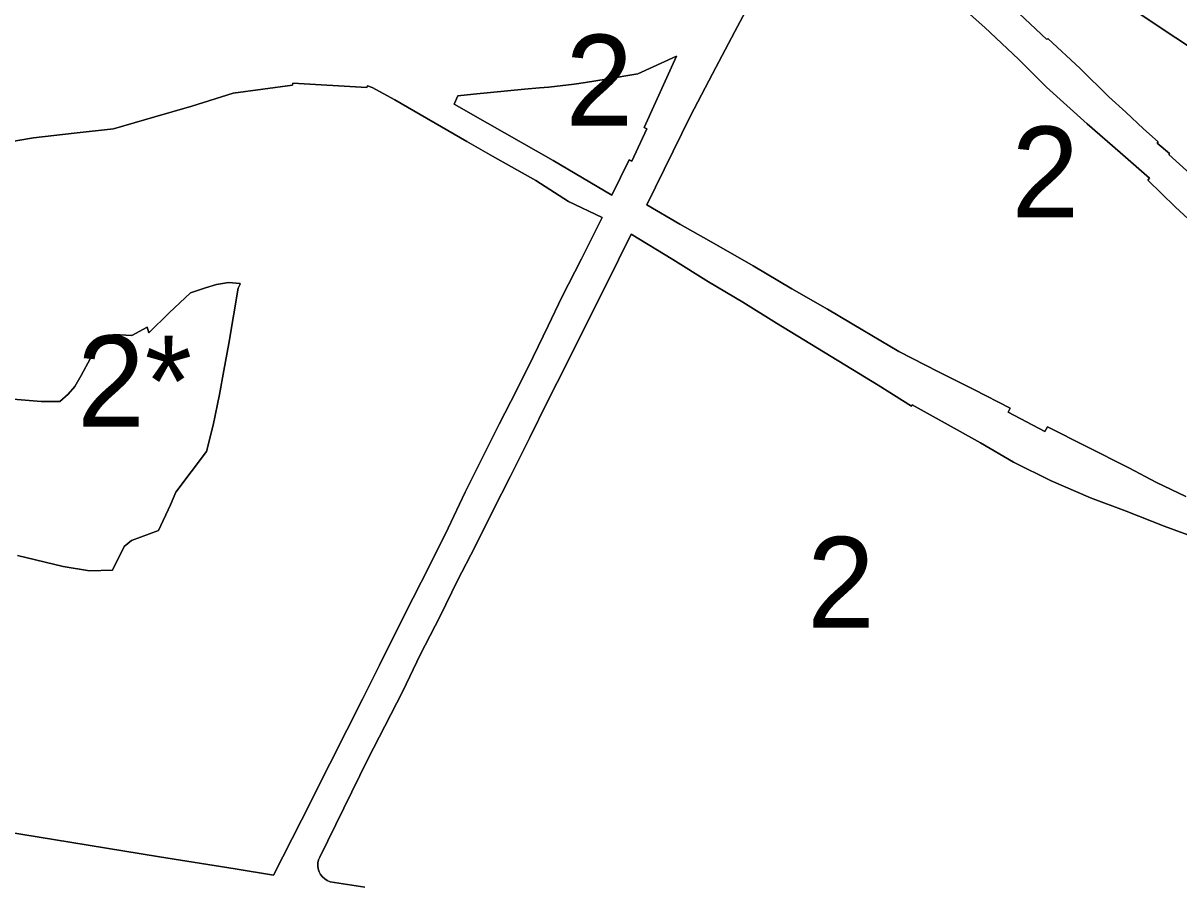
# Model space of a CAD drawing. Extents: x 598968 to 613553, y 4409678 to 4430833.
# Drawn here: x 607715.2 to 607867.8, y 4416289 to 4416402.7 of the extents above; entities that cross this region are included whole.
import ezdxf

# ---------------------------------------------------------------- set-up
doc = ezdxf.new("R2010")
doc.units = 0
for name, color, linetype in [('1', 7, 'Continuous'), ('ZONA 2. CARRERS DE CASES. Cases de trast', 7, 'Continuous'), ("ZONA 2_. CARRERS DE CASES. Afectades a ús d'aparcament", 7, 'Continuous')]:
    doc.layers.add(name, color=color, linetype=linetype)

msp = doc.modelspace()

# ---------------------------------------------------------------- linework, layer by layer
at = {"layer": '1'}
for points in [[(607833.2751, 4416410.0535), (607842.1551, 4416402.1438), (607846.625, 4416397.9639), (607850.315, 4416394.264), (607855.6849, 4416389.4042), (607860.0249, 4416385.6143), (607863.9149, 4416382.2344), (607863.6749, 4416381.9644), (607867.3149, 4416378.4645), (607877.7248, 4416368.8498)], [(607868.715, 4416340.245), (607864.8212, 4416342.0745), (607861.175, 4416344.0349), (607855.6051, 4416346.8447), (607850.4351, 4416349.4546), (607850.0951, 4416348.8246), (607845.2338, 4416351.3794), (607845.5063, 4416351.9116), (607840.7152, 4416354.3643), (607836.0753, 4416356.7042), (607830.8053, 4416359.3541), (607826.0654, 4416362.204), (607821.3954, 4416364.9639), (607816.6755, 4416367.6537), (607811.5655, 4416370.6636), (607806.7556, 4416373.4435), (607801.8956, 4416376.1734), (607797.5557, 4416378.7133), (607803.3055, 4416390.4532), (607806.2155, 4416396.0332), (607809.162, 4416401.5938), (607811.6354, 4416406.2732)], [(607869.2898, 4416382.8195), (607866.4748, 4416385.3744), (607866.5548, 4416385.4844), (607864.9326, 4416386.8721), (607865.0703, 4416387.033), (607863.1349, 4416388.7443), (607860.7749, 4416390.9542), (607858.5349, 4416392.9642), (607854.7549, 4416396.7141), (607850.5011, 4416400.6895), (607850.365, 4416400.5439), (607845.9477, 4416404.682)], [(607860.5903, 4416405.2824), (607864.9348, 4416402.4042), (607869.8548, 4416399.1343)], [(607711.1266, 4416386.6417), (607716.5566, 4416387.5518), (607721.9565, 4416388.1918), (607727.1364, 4416388.7419), (607732.5864, 4416390.332), (607737.4724, 4416391.7408), (607742.9162, 4416393.4522), (607750.7861, 4416394.5123), (607750.8161, 4416394.7623), (607760.596, 4416394.2225), (607760.686, 4416394.4225), (607761.276, 4416394.2325), (607764.256, 4416392.5825), (607773.7959, 4416387.0828), (607777.1559, 4416385.1629), (607782.8958, 4416381.953), (607787.2058, 4416379.1831), (607791.6657, 4416377.0432), (607788.9358, 4416371.6132), (607786.3458, 4416366.5432), (607784.5159, 4416362.7432), (607782.5459, 4416358.6633), (607780.3259, 4416354.2333), (607778.0464, 4416349.7726), (607773.5661, 4416340.8134), (607771.3161, 4416336.0834), (607768.8661, 4416331.0734), (607766.7162, 4416326.8834), (607764.6262, 4416322.7634), (607762.2563, 4416318.0034), (607759.9963, 4416313.4834), (607757.9263, 4416309.4035), (607755.7164, 4416304.9835), (607754.4414, 4416302.4735), (607753.1664, 4416299.9635), (607748.2765, 4416290.2935), (607743.1766, 4416291.1034), (607733.2267, 4416292.6732), (607723.7818, 4416294.238), (607708.397, 4416296.7227)], [(607760.3364, 4416288.6937), (607755.7264, 4416289.3937), (607755.3576, 4416289.5517), (607755.0211, 4416289.77), (607754.7266, 4416290.0425), (607754.4828, 4416290.3611), (607754.2968, 4416290.7166), (607754.1739, 4416291.0985), (607754.1177, 4416291.4958), (607754.13, 4416291.8968), (607754.2104, 4416292.2899), (607754.3564, 4416292.6636), (607760.7263, 4416305.5836), (607762.9663, 4416309.9535), (607765.3362, 4416314.5635), (607767.6362, 4416319.3435), (607770.2462, 4416324.4435), (607772.5561, 4416329.1635), (607774.8761, 4416333.6635), (607777.226, 4416338.3435), (607779.536, 4416342.9334), (607782.0859, 4416348.0334), (607784.4459, 4416352.7734), (607786.9758, 4416357.7733), (607789.0058, 4416361.9033), (607791.2858, 4416366.4133), (607793.7857, 4416371.4833), (607795.4957, 4416374.8433), (607800.9678, 4416371.5254), (607805.6956, 4416368.5835), (607810.2056, 4416365.8637), (607814.6755, 4416363.1238), (607823.6954, 4416357.614), (607828.1054, 4416354.9241), (607832.4715, 4416352.1603), (607832.5753, 4416352.3242), (607836.9353, 4416349.9243), (607841.6053, 4416347.3144), (607845.9552, 4416344.7745), (607850.9152, 4416342.3247), (607856.1051, 4416340.0548), (607860.8251, 4416338.2849), (607865.845, 4416336.345), (607870.285, 4416334.7051)]]:
    msp.add_lwpolyline(points, dxfattribs=at)
msp.add_lwpolyline([(607787.9657, 4416394.6429), (607789.4597, 4416394.8879), (607792.1757, 4416395.333), (607796.3511, 4416396.0226), (607801.4755, 4416398.3431), (607797.1756, 4416388.9532), (607797.5556, 4416388.7632), (607795.5457, 4416384.4732), (607795.2157, 4416384.6532), (607792.9057, 4416380.0032), (607785.1758, 4416384.573), (607776.4959, 4416389.4928), (607772.1245, 4416392.023), (607772.6059, 4416393.1027), (607774.6459, 4416393.3527), (607781.4058, 4416394.0028), (607783.3729, 4416394.1571), (607784.5957, 4416394.2529)], close=True, dxfattribs=at)
at = {"layer": 'ZONA 2. CARRERS DE CASES. Cases de trast'}
for points in [[(607877.7248, 4416368.8498), (607867.3149, 4416378.4645), (607863.6749, 4416381.9644), (607863.9149, 4416382.2344), (607860.0249, 4416385.6143), (607855.6849, 4416389.4042), (607850.315, 4416394.264), (607846.625, 4416397.9639), (607842.1551, 4416402.1438), (607833.2751, 4416410.0535)], [(607811.6354, 4416406.2732), (607809.162, 4416401.5938), (607806.2155, 4416396.0332), (607803.3055, 4416390.4532), (607797.5557, 4416378.7133), (607801.8956, 4416376.1734), (607806.7556, 4416373.4435), (607811.5655, 4416370.6636), (607816.6755, 4416367.6537), (607821.3954, 4416364.9639), (607826.0654, 4416362.204), (607830.8053, 4416359.3541), (607836.0753, 4416356.7042), (607840.7152, 4416354.3643), (607845.5063, 4416351.9116), (607845.2338, 4416351.3794), (607850.0951, 4416348.8246), (607850.4351, 4416349.4546), (607855.6051, 4416346.8447), (607861.175, 4416344.0349), (607864.8212, 4416342.0745), (607868.715, 4416340.245)], [(607845.9477, 4416404.682), (607850.365, 4416400.5439), (607850.5011, 4416400.6895), (607854.7549, 4416396.7141), (607858.5349, 4416392.9642), (607860.7749, 4416390.9542), (607863.1349, 4416388.7443), (607865.0703, 4416387.033), (607864.9326, 4416386.8721), (607866.5548, 4416385.4844), (607866.4748, 4416385.3744), (607869.2898, 4416382.8195)], [(607869.8548, 4416399.1343), (607864.9348, 4416402.4042), (607860.5903, 4416405.2824)], [(607708.397, 4416296.7227), (607723.7818, 4416294.238), (607733.2267, 4416292.6732), (607743.1766, 4416291.1034), (607748.2765, 4416290.2935), (607753.1664, 4416299.9635), (607754.4414, 4416302.4735), (607755.7164, 4416304.9835), (607757.9263, 4416309.4035), (607759.9963, 4416313.4834), (607762.2563, 4416318.0034), (607764.6262, 4416322.7634), (607766.7162, 4416326.8834), (607768.8661, 4416331.0734), (607771.3161, 4416336.0834), (607773.5661, 4416340.8134), (607778.0464, 4416349.7726), (607780.3259, 4416354.2333), (607782.5459, 4416358.6633), (607784.5159, 4416362.7432), (607786.3458, 4416366.5432), (607788.9358, 4416371.6132), (607791.6657, 4416377.0432), (607787.2058, 4416379.1831), (607782.8958, 4416381.953), (607777.1559, 4416385.1629), (607773.7959, 4416387.0828), (607764.256, 4416392.5825), (607761.276, 4416394.2325), (607760.686, 4416394.4225), (607760.596, 4416394.2225), (607750.8161, 4416394.7623), (607750.7861, 4416394.5123), (607742.9162, 4416393.4522), (607737.4724, 4416391.7408), (607732.5864, 4416390.332), (607727.1364, 4416388.7419), (607721.9565, 4416388.1918), (607716.5566, 4416387.5518), (607711.1266, 4416386.6417)], [(607870.285, 4416334.7051), (607865.845, 4416336.345), (607860.8251, 4416338.2849), (607856.1051, 4416340.0548), (607850.9152, 4416342.3247), (607845.9552, 4416344.7745), (607841.6053, 4416347.3144), (607836.9353, 4416349.9243), (607832.5753, 4416352.3242), (607832.4715, 4416352.1603), (607828.1054, 4416354.9241), (607823.6954, 4416357.614), (607814.6755, 4416363.1238), (607810.2056, 4416365.8637), (607805.6956, 4416368.5835), (607800.9678, 4416371.5254), (607795.4957, 4416374.8433), (607793.7857, 4416371.4833), (607791.2858, 4416366.4133), (607789.0058, 4416361.9033), (607786.9758, 4416357.7733), (607784.4459, 4416352.7734), (607782.0859, 4416348.0334), (607779.536, 4416342.9334), (607777.226, 4416338.3435), (607774.8761, 4416333.6635), (607772.5561, 4416329.1635), (607770.2462, 4416324.4435), (607767.6362, 4416319.3435), (607765.3362, 4416314.5635), (607762.9663, 4416309.9535), (607760.7263, 4416305.5836), (607754.3564, 4416292.6636), (607754.2104, 4416292.2899), (607754.13, 4416291.8968), (607754.1177, 4416291.4958), (607754.1739, 4416291.0985), (607754.2968, 4416290.7166), (607754.4828, 4416290.3611), (607754.7266, 4416290.0425), (607755.0211, 4416289.77), (607755.3576, 4416289.5517), (607755.7264, 4416289.3937), (607760.3364, 4416288.6937)], [(607713.8967, 4416353.0876), (607717.5988, 4416352.7577), (607720.0666, 4416352.7877), (607721.1336, 4416353.7251), (607722.0117, 4416354.773), (607722.8666, 4416356.1877), (607724.0666, 4416358.3977), (607724.9781, 4416359.718), (607726.4965, 4416361.4277), (607727.2151, 4416361.6344), (607729.5365, 4416361.5028), (607731.5665, 4416362.5978), (607731.8009, 4416361.8498), (607734.4864, 4416364.4778), (607737.309, 4416367.1211), (607739.2796, 4416367.7718), (607740.7463, 4416368.2079), (607742.3363, 4416368.4779), (607743.8563, 4416368.348), (607743.8161, 4416368.2659), (607743.8563, 4416368.2625), (607743.6063, 4416367.7525), (607742.3663, 4416360.4325), (607741.6968, 4416356.8855), (607741.1464, 4416353.6826), (607740.3108, 4416349.6643), (607739.3914, 4416346.1927), (607735.3565, 4416340.8027), (607734.6765, 4416339.1227), (607733.0565, 4416335.7627), (607729.5266, 4416334.4227), (607728.5566, 4416333.6627), (607727.0066, 4416330.5027), (607723.9667, 4416330.4426), (607720.4967, 4416331.0025), (607714.4768, 4416332.4624)]]:
    msp.add_lwpolyline(points, dxfattribs=at)
msp.add_lwpolyline([(607797.5556, 4416388.7632), (607797.1756, 4416388.9532), (607801.4755, 4416398.3431), (607796.3511, 4416396.0226), (607792.1757, 4416395.333), (607789.4597, 4416394.8879), (607787.9657, 4416394.6429), (607784.5957, 4416394.2529), (607783.3729, 4416394.1571), (607781.4058, 4416394.0028), (607774.6459, 4416393.3527), (607772.6059, 4416393.1027), (607772.1245, 4416392.023), (607776.4959, 4416389.4928), (607785.1758, 4416384.573), (607792.9057, 4416380.0032), (607795.2157, 4416384.6532), (607795.5457, 4416384.4732)], close=True, dxfattribs=at)
at = {"layer": "ZONA 2_. CARRERS DE CASES. Afectades a ús d'aparcament"}
msp.add_lwpolyline([(607714.4768, 4416332.4624), (607720.4967, 4416331.0025), (607723.9667, 4416330.4426), (607727.0066, 4416330.5027), (607728.5566, 4416333.6627), (607729.5266, 4416334.4227), (607733.0565, 4416335.7627), (607734.6765, 4416339.1227), (607735.3565, 4416340.8027), (607739.3914, 4416346.1927), (607740.3108, 4416349.6643), (607741.1464, 4416353.6826), (607741.6968, 4416356.8855), (607742.3663, 4416360.4325), (607743.6063, 4416367.7525), (607743.8563, 4416368.2625), (607743.8161, 4416368.2659), (607743.8563, 4416368.348), (607742.3363, 4416368.4779), (607740.7463, 4416368.2079), (607739.2796, 4416367.7718), (607737.309, 4416367.1211), (607734.4864, 4416364.4778), (607731.8009, 4416361.8498), (607731.5665, 4416362.5978), (607729.5365, 4416361.5028), (607727.2151, 4416361.6344), (607726.4965, 4416361.4277), (607724.9781, 4416359.718), (607724.0666, 4416358.3977), (607722.8666, 4416356.1877), (607722.0117, 4416354.773), (607721.1336, 4416353.7251), (607720.0666, 4416352.7877), (607717.5988, 4416352.7577), (607713.8967, 4416353.0876)], dxfattribs=at)

# ---------------------------------------------------------------- texts
at = {"layer": 'ZONA 2. CARRERS DE CASES. Cases de trast'}
for p in [(607786.8, 4416389.1732), (607845.6852, 4416377.0643), (607818.7063, 4416322.9146)]:
    msp.add_text('2', height=12, dxfattribs=at).set_placement(p)
at = {"layer": "ZONA 2_. CARRERS DE CASES. Afectades a ús d'aparcament"}
msp.add_text('2*', height=12, dxfattribs=at).set_placement((607722.3366, 4416349.4603))

doc.saveas('drawing.dxf')
